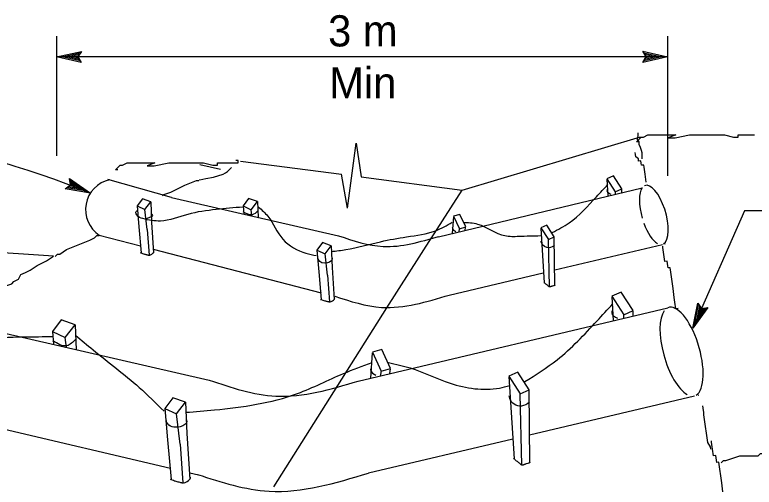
# Model space of a CAD drawing. Extents: x 6707406 to 6714471, y 1868570 to 1872341.
# Drawn here: x 6707735.3 to 6707906.2, y 1870270 to 1870379.1 of the extents above; entities that cross this region are included whole.
import ezdxf

# ---------------------------------------------------------------- set-up
doc = ezdxf.new("R2010")
doc.units = 0
for name, color, linetype in [('56 Stg 3 Anno', 7, 'Continuous'), ('57 Undefined', 7, 'Continuous'), ('60 Nongeo Data', 7, 'Continuous')]:
    doc.layers.add(name, color=color, linetype=linetype)

msp = doc.modelspace()

# ---------------------------------------------------------------- linework, layer by layer
at = {"layer": '56 Stg 3 Anno'}
for p, q in [((6707744.92, 1870374.22), (6707744.92, 1870346.59)), ((6707886.21, 1870374.22), (6707886.21, 1870341.97)), ((6707744.93, 1870369.42), (6707750.7, 1870370.68)), ((6707750.7, 1870370.68), (6707749.92, 1870369.4)), ((6707750.7, 1870370.68), (6707750.7, 1870370.68)), ((6707881.22, 1870369.42), (6707880.45, 1870370.7)), ((6707880.45, 1870370.7), (6707880.45, 1870370.7)), ((6707880.45, 1870370.7), (6707886.21, 1870369.41)), ((6707886.21, 1870369.41), (6707744.92, 1870369.42)), ((6707750.69, 1870368.11), (6707744.93, 1870369.42)), ((6707744.93, 1870369.42), (6707744.93, 1870369.42)), ((6707750.48, 1870368.46), (6707746.26, 1870369.42)), ((6707746.27, 1870369.42), (6707750.47, 1870370.33)), ((6707747.58, 1870369.41), (6707750.3, 1870370)), ((6707750.26, 1870368.8), (6707747.58, 1870369.41)), ((6707748.91, 1870369.4), (6707750.07, 1870369.66)), ((6707750.09, 1870369.14), (6707748.91, 1870369.4)), ((6707749.92, 1870369.4), (6707750.69, 1870368.11)), ((6707880.45, 1870368.14), (6707881.22, 1870369.42)), ((6707886.21, 1870369.41), (6707880.45, 1870368.14)), ((6707880.66, 1870370.36), (6707884.88, 1870369.42)), ((6707884.87, 1870369.41), (6707880.67, 1870368.48)), ((6707883.56, 1870369.42), (6707880.84, 1870368.82)), ((6707880.88, 1870370.02), (6707883.56, 1870369.42)), ((6707881.05, 1870369.68), (6707882.23, 1870369.42)), ((6707882.23, 1870369.42), (6707881.07, 1870369.16)), ((6707886.21, 1870369.41), (6707886.21, 1870369.41)), ((6707750.69, 1870368.11), (6707750.69, 1870368.11)), ((6707880.45, 1870368.14), (6707880.45, 1870368.14)), ((6707748.17, 1870339.83), (6707747.94, 1870341.31)), ((6707747.94, 1870341.31), (6707747.94, 1870341.31)), ((6707747.94, 1870341.31), (6707752.8, 1870337.97)), ((6707748.01, 1870340.92), (6707751.57, 1870338.47)), ((6707748.08, 1870340.52), (6707750.34, 1870338.96)), ((6707748.12, 1870340.14), (6707749.11, 1870339.46)), ((6707746.98, 1870338.94), (6707748.17, 1870339.83)), ((6707752.8, 1870337.97), (6707746.98, 1870338.94)), ((6707746.98, 1870338.94), (6707746.98, 1870338.94)), ((6707751.56, 1870338.47), (6707747.32, 1870339.17)), ((6707750.34, 1870338.96), (6707747.6, 1870339.42)), ((6707749.11, 1870339.46), (6707747.94, 1870339.65)), ((6707752.8, 1870337.97), (6707752.8, 1870337.97)), ((6707903.94, 1870333.87), (6707892, 1870306.77)), ((6707954.76, 1870333.87), (6707903.94, 1870333.87)), ((6707892, 1870306.77), (6707893.15, 1870312.55)), ((6707893.15, 1870312.55), (6707893.15, 1870312.55)), ((6707893.15, 1870312.55), (6707894.01, 1870311.34)), ((6707895.5, 1870311.52), (6707892, 1870306.77)), ((6707892.53, 1870307.99), (6707893.37, 1870312.21)), ((6707895.1, 1870311.47), (6707892.53, 1870307.98)), ((6707893.07, 1870309.19), (6707893.61, 1870311.92)), ((6707894.69, 1870311.4), (6707893.07, 1870309.19)), ((6707893.6, 1870310.41), (6707893.84, 1870311.57)), ((6707894.32, 1870311.38), (6707893.6, 1870310.41)), ((6707894.01, 1870311.34), (6707895.5, 1870311.52)), ((6707895.5, 1870311.52), (6707895.5, 1870311.52)), ((6707892, 1870306.77), (6707892, 1870306.77))]:
    msp.add_line(p, q, dxfattribs=at)
msp.add_ellipse((6707692.49, 1870326.8), major_axis=(94.95, -17.15), ratio=0.279834, start_param=0.934096, end_param=2.086505, dxfattribs=at)
at = {"layer": '60 Nongeo Data'}
for p, q in [((6707812.25, 1870334.5), (6707814.21, 1870349.45)), ((6707814.21, 1870349.45), (6707815.39, 1870341.71)), ((6707812.25, 1870334.5), (6707810.8, 1870342.3)), ((6707771.53, 1870336.96), (6707756.84, 1870341.13)), ((6707831.54, 1870327.45), (6707838.68, 1870338.66)), ((6707833.26, 1870327.86), (6707880.33, 1870339.18)), ((6707771.53, 1870336.96), (6707810.12, 1870328.11)), ((6707766.73, 1870335.95), (6707766.94, 1870331.19)), ((6707791.39, 1870335.99), (6707791.55, 1870332.34)), ((6707754.85, 1870328.22), (6707764.35, 1870325.76)), ((6707765.91, 1870329.52), (6707766.35, 1870323.63)), ((6707821.34, 1870311.42), (6707831.63, 1870327.59)), ((6707885.56, 1870326.22), (6707885.65, 1870326.24)), ((6707767.26, 1870325), (6707806.09, 1870314.93)), ((6707808.47, 1870325.81), (6707808.69, 1870320.79)), ((6707860.11, 1870320.2), (6707885, 1870326.11)), ((6707764.54, 1870324.13), (6707764.39, 1870324.32)), ((6707835.73, 1870314.42), (6707857.43, 1870319.57)), ((6707807.61, 1870319.03), (6707808.08, 1870312.84)), ((6707809.96, 1870293.53), (6707821.34, 1870311.42)), ((6707814.7, 1870294.54), (6707886.25, 1870311.46)), ((6707718.18, 1870308.99), (6707780.25, 1870294.75)), ((6707749.27, 1870307.56), (6707749.52, 1870301.77)), ((6707795.21, 1870270.09), (6707809.96, 1870293.53)), ((6707854.3, 1870282.12), (6707892.42, 1870291.13)), ((6707893.26, 1870291.31), (6707893.39, 1870291.33)), ((6707709.15, 1870289.03), (6707771.34, 1870274.43)), ((6707774.76, 1870289.64), (6707775.07, 1870282.46)), ((6707817.03, 1870273.32), (6707850.44, 1870281.21)), ((6707773.52, 1870279.94), (6707774.19, 1870271.07)), ((6707775.77, 1870273.38), (6707777.75, 1870272.92))]:
    msp.add_line(p, q, dxfattribs=at)
for points in [[(6707880.34, 1870345.86), (6707880.34, 1870347.23), (6707880.2, 1870347.78), (6707879.92, 1870348.46), (6707879.65, 1870349.15), (6707879.65, 1870349.42), (6707879.65, 1870349.7), (6707879.51, 1870350.11), (6707879.24, 1870350.25), (6707879.24, 1870350.38), (6707879.24, 1870350.52), (6707879.24, 1870350.66), (6707879.24, 1870350.79), (6707879.38, 1870351.07), (6707879.38, 1870351.2), (6707879.38, 1870351.34), (6707879.38, 1870351.48), (6707879.38, 1870351.62), (6707879.38, 1870351.75), (6707879.38, 1870351.85)], [(6707815.39, 1870341.71), (6707838.68, 1870338.66), (6707879.9, 1870350.92)], [(6707879.52, 1870349.8), (6707878.98, 1870349.8), (6707879.52, 1870350.33), (6707880.05, 1870350.86), (6707880.59, 1870350.86), (6707881.66, 1870351.4), (6707882.73, 1870351.4), (6707883.26, 1870351.4), (6707884.33, 1870351.4), (6707885.41, 1870351.4), (6707885.94, 1870351.4), (6707886.48, 1870351.4), (6707887.55, 1870351.4), (6707888.08, 1870351.4), (6707886.34, 1870350.73), (6707887.95, 1870350.73), (6707891.29, 1870351.4), (6707891.83, 1870351.4), (6707892.36, 1870351.4), (6707892.9, 1870351.4), (6707893.43, 1870351.4), (6707893.97, 1870351.4), (6707894.5, 1870351.4), (6707895.04, 1870351.4), (6707895.57, 1870351.4), (6707896.65, 1870351.4), (6707897.72, 1870351.4), (6707898.79, 1870351.4), (6707899.32, 1870351.4), (6707901.46, 1870350.86), (6707902.53, 1870350.86), (6707902.53, 1870351.4), (6707903.6, 1870351.4), (6707904.14, 1870351.4), (6707904.67, 1870351.4), (6707905.21, 1870351.4), (6707905.74, 1870351.4), (6707906.28, 1870351.4)], [(6707881.24, 1870340.45), (6707880.99, 1870342.32), (6707880.92, 1870342.85), (6707880.85, 1870343.38), (6707880.78, 1870343.91), (6707880.71, 1870344.44), (6707880.18, 1870344.37), (6707880.11, 1870344.9), (6707880.04, 1870345.43), (6707879.51, 1870345.35), (6707879.44, 1870345.88), (6707878.83, 1870346.34), (6707878.76, 1870346.87), (6707878.71, 1870347.31)], [(6707759.13, 1870343.33), (6707758.6, 1870343.33), (6707759.13, 1870343.86), (6707759.67, 1870344.4), (6707760.2, 1870344.4), (6707761.27, 1870344.93), (6707762.34, 1870344.93), (6707762.88, 1870344.93), (6707763.95, 1870344.93), (6707765.02, 1870344.93), (6707765.55, 1870344.93), (6707766.09, 1870344.93), (6707767.16, 1870344.93), (6707767.69, 1870344.93), (6707765.95, 1870344.26), (6707767.56, 1870344.26), (6707770.91, 1870344.93), (6707771.44, 1870344.93), (6707771.98, 1870344.93), (6707772.51, 1870344.93), (6707773.05, 1870344.93), (6707773.58, 1870344.93), (6707774.12, 1870344.93), (6707774.65, 1870344.93), (6707775.19, 1870344.93), (6707776.26, 1870344.93), (6707777.33, 1870344.93), (6707778.4, 1870344.93), (6707778.93, 1870344.93), (6707781.08, 1870344.4), (6707782.15, 1870344.4), (6707782.15, 1870344.93), (6707783.22, 1870344.93), (6707783.75, 1870344.93), (6707784.29, 1870344.93), (6707784.82, 1870344.93), (6707785.36, 1870344.93), (6707785.89, 1870344.93), (6707786.43, 1870344.93), (6707786.43, 1870344.93), (6707786.96, 1870344.93), (6707786.96, 1870345.47), (6707786.43, 1870345.47)], [(6707787.52, 1870345.35), (6707810.8, 1870342.3)], [(6707778.07, 1870341.01), (6707778.01, 1870341.01), (6707778.07, 1870341.01), (6707778.79, 1870341.18), (6707779.46, 1870341.29), (6707781.25, 1870341.62), (6707783.49, 1870342.35), (6707784.05, 1870342.63), (6707784.49, 1870342.96), (6707785.11, 1870343.52), (6707785.41, 1870343.86)], [(6707778.05, 1870344.55), (6707782.83, 1870343.47)], [(6707769.45, 1870337.3), (6707769.8, 1870337.65), (6707771.41, 1870338.18), (6707772.48, 1870338.72), (6707773.55, 1870339.25), (6707774.62, 1870339.79), (6707777.29, 1870340.86), (6707777.83, 1870340.86), (6707777.84, 1870340.86)], [(6707872.16, 1870341.18), (6707872.4, 1870337.34)], [(6707874.13, 1870337.74), (6707874.12, 1870338.24)], [(6707875.62, 1870338.09), (6707875.61, 1870338.92)], [(6707763.58, 1870334.99), (6707763.99, 1870330.2)], [(6707788.07, 1870334.98), (6707788.23, 1870333.13)], [(6707765.89, 1870329.52), (6707765.91, 1870329.52), (6707765.36, 1870334.17)], [(6707790.12, 1870332.68), (6707789.95, 1870334.12)], [(6707836.72, 1870332.55), (6707836.42, 1870328.64)], [(6707763.99, 1870330.2), (6707764.54, 1870324.13)], [(6707766.94, 1870331.19), (6707767.38, 1870324.18)], [(6707838.02, 1870329.02), (6707838.1, 1870329.68)], [(6707839.42, 1870329.35), (6707839.52, 1870330.1)], [(6707856.89, 1870329.85), (6707857.7, 1870317.24)], [(6707744.64, 1870323.34), (6707745.15, 1870323.85), (6707745.69, 1870323.85), (6707747.29, 1870324.92), (6707749.97, 1870325.99), (6707752.65, 1870327.06), (6707753.72, 1870327.59), (6707754.25, 1870328.13), (6707754.81, 1870328.13)], [(6707858.89, 1870316.27), (6707858.66, 1870327.2)], [(6707860.12, 1870316.66), (6707860.01, 1870327.82)], [(6707718.5, 1870308.92), (6707720.15, 1870310.57), (6707721.75, 1870311.1), (6707722.82, 1870311.63), (6707723.89, 1870312.17), (6707724.96, 1870312.7), (6707727.64, 1870313.77), (6707728.18, 1870313.77), (6707729.25, 1870314.31), (6707729.25, 1870314.84), (6707729.78, 1870314.84), (6707731.39, 1870315.38), (6707732.99, 1870316.45), (6707734.6, 1870316.98), (6707735.13, 1870317.51), (6707736.2, 1870318.05), (6707736.74, 1870319.12), (6707737.81, 1870319.65), (6707738.88, 1870320.19), (6707740.49, 1870321.26), (6707742.63, 1870322.32), (6707744.23, 1870323.39), (6707726.78, 1870324.51)], [(6707805.15, 1870324.8), (6707805.59, 1870319.75)], [(6707888.62, 1870311.27), (6707888.09, 1870311.2), (6707888.02, 1870311.73), (6707887.95, 1870312.26), (6707887.88, 1870312.79), (6707887.81, 1870313.32), (6707887.74, 1870313.84), (6707887.46, 1870315.96), (6707887.31, 1870317.02), (6707887.24, 1870317.55), (6707887.17, 1870318.08), (6707887.1, 1870318.61), (6707887.03, 1870319.14), (6707886.96, 1870319.67), (6707886.89, 1870320.2), (6707886.82, 1870320.73), (6707886.29, 1870320.66), (6707886.22, 1870321.19), (6707886.15, 1870321.72), (6707886.07, 1870322.25), (6707885.54, 1870322.18), (6707885.47, 1870322.71), (6707885.4, 1870323.24), (6707885.33, 1870323.77), (6707885.26, 1870324.3), (6707885.19, 1870324.83), (6707885.12, 1870325.36), (6707885.08, 1870325.68)], [(6707764.37, 1870324.18), (6707764.52, 1870324.13), (6707764.87, 1870324.03), (6707765.07, 1870323.93), (6707765.12, 1870323.93), (6707765.27, 1870323.88), (6707765.42, 1870323.83), (6707765.57, 1870323.78), (6707765.72, 1870323.78), (6707765.87, 1870323.73), (6707765.98, 1870323.68), (6707766.13, 1870323.68), (6707766.18, 1870323.63), (6707766.23, 1870323.63), (6707766.43, 1870323.63), (6707766.48, 1870323.58), (6707766.53, 1870323.63), (6707766.68, 1870323.68), (6707766.99, 1870323.83)], [(6707766.98, 1870323.83), (6707767.18, 1870323.98), (6707767.33, 1870324.13), (6707767.38, 1870324.18), (6707767.44, 1870324.23), (6707767.49, 1870324.38), (6707767.54, 1870324.38), (6707767.54, 1870324.38), (6707767.49, 1870324.38)], [(6707807.58, 1870319.04), (6707807.61, 1870319.03), (6707807.03, 1870323.93)], [(6707805.59, 1870319.75), (6707806.16, 1870313.36)], [(6707808.69, 1870320.79), (6707809.16, 1870313.42)], [(6707860.15, 1870316.68), (6707860.14, 1870316.67), (6707860.11, 1870316.65), (6707860.03, 1870316.63), (6707859.98, 1870316.61), (6707859.88, 1870316.57), (6707859.81, 1870316.54), (6707859.62, 1870316.5), (6707859.53, 1870316.48), (6707859.44, 1870316.44), (6707859.41, 1870316.43), (6707859.35, 1870316.4), (6707859.32, 1870316.4), (6707859.28, 1870316.38), (6707859.25, 1870316.38), (6707859.22, 1870316.36), (6707859.19, 1870316.35), (6707859.15, 1870316.33), (6707859.12, 1870316.31), (6707859.09, 1870316.3), (6707859.08, 1870316.29), (6707859.03, 1870316.28), (6707859.01, 1870316.27), (6707858.98, 1870316.27), (6707858.96, 1870316.27), (6707858.94, 1870316.27), (6707858.93, 1870316.27), (6707858.91, 1870316.27), (6707858.9, 1870316.26), (6707858.89, 1870316.26), (6707858.87, 1870316.26), (6707858.87, 1870316.27), (6707858.86, 1870316.28), (6707858.85, 1870316.3), (6707858.82, 1870316.34), (6707858.74, 1870316.4), (6707858.65, 1870316.49), (6707858.55, 1870316.57), (6707858.43, 1870316.65), (6707858.34, 1870316.74), (6707858.24, 1870316.82), (6707858.09, 1870316.91), (6707857.98, 1870316.99), (6707857.9, 1870317.06), (6707857.83, 1870317.13), (6707857.77, 1870317.17), (6707857.72, 1870317.23), (6707857.67, 1870317.27), (6707857.65, 1870317.28), (6707857.64, 1870317.28), (6707857.64, 1870317.29), (6707857.64, 1870317.29)], [(6707805.98, 1870313.42), (6707806.14, 1870313.37), (6707806.51, 1870313.26), (6707806.72, 1870313.15), (6707806.78, 1870313.15), (6707806.94, 1870313.1), (6707807.1, 1870313.05), (6707807.25, 1870313), (6707807.41, 1870313), (6707807.57, 1870312.94), (6707807.68, 1870312.89), (6707807.84, 1870312.89), (6707807.89, 1870312.84), (6707807.94, 1870312.84), (6707808.16, 1870312.84), (6707808.21, 1870312.78), (6707808.26, 1870312.84), (6707808.42, 1870312.89), (6707808.75, 1870313.05)], [(6707808.74, 1870313.05), (6707808.95, 1870313.21), (6707809.11, 1870313.37), (6707809.16, 1870313.42), (6707809.21, 1870313.47), (6707809.27, 1870313.63), (6707809.32, 1870313.63), (6707809.32, 1870313.63), (6707809.27, 1870313.63)], [(6707873.27, 1870314.02), (6707873.62, 1870308.53)], [(6707876.09, 1870309.1), (6707876.08, 1870309.81)], [(6707878.22, 1870309.6), (6707878.21, 1870310.79)], [(6707744.01, 1870305.96), (6707744.26, 1870303.03)], [(6707747.25, 1870302.31), (6707746.98, 1870304.59)], [(6707817.95, 1870301.1), (6707817.5, 1870295.21)], [(6707822.02, 1870296.27), (6707822.17, 1870297.41)], [(6707819.91, 1870295.78), (6707820.03, 1870296.77)], [(6707849.5, 1870295.58), (6707850.72, 1870276.58)], [(6707854.37, 1870275.69), (6707854.19, 1870292.51)], [(6707852.51, 1870275.11), (6707852.16, 1870291.58)], [(6707896.2, 1870278.85), (6707896.13, 1870279.38), (6707895.46, 1870280.37), (6707895.32, 1870281.42), (6707895.17, 1870282.48), (6707894.96, 1870284.07), (6707894.82, 1870285.13), (6707894.68, 1870286.19), (6707894.61, 1870286.72), (6707894.54, 1870287.25), (6707894.39, 1870288.31), (6707894.32, 1870288.84)], [(6707770.01, 1870288.19), (6707770.63, 1870280.97)], [(6707773.49, 1870279.95), (6707773.52, 1870279.94), (6707772.7, 1870286.96)], [(6707775.07, 1870282.46), (6707775.74, 1870271.89)], [(6707770.63, 1870280.97), (6707771.46, 1870271.81)], [(6707898.99, 1870268.93), (6707898.71, 1870271.05), (6707898.57, 1870272.11), (6707898.5, 1870272.64), (6707898.42, 1870273.17), (6707898.35, 1870273.69), (6707898.28, 1870274.22), (6707898.21, 1870274.75), (6707898.14, 1870275.28), (6707898.07, 1870275.81), (6707897.54, 1870275.74), (6707897.47, 1870276.27), (6707897.4, 1870276.8), (6707897.33, 1870277.33), (6707896.8, 1870277.26), (6707896.73, 1870277.79), (6707896.66, 1870278.32), (6707896.58, 1870278.85), (6707896.51, 1870279.38), (6707896.44, 1870279.91), (6707896.37, 1870280.44), (6707896.33, 1870280.76)], [(6707898.59, 1870275.66), (6707899.12, 1870276.19), (6707899.66, 1870276.19), (6707901.26, 1870276.73), (6707902.87, 1870277.26), (6707903.41, 1870277.26), (6707903.94, 1870277.26), (6707904.48, 1870277.26), (6707905.55, 1870277.26), (6707906.08, 1870277.26), (6707907.15, 1870277.26), (6707907.69, 1870277.8), (6707908.76, 1870277.8), (6707909.29, 1870277.8), (6707910.36, 1870277.8), (6707911.43, 1870278.33), (6707913.04, 1870278.33), (6707913.58, 1870278.87), (6707914.11, 1870278.87), (6707914.65, 1870278.87), (6707915.18, 1870278.87), (6707915.18, 1870278.87), (6707915.72, 1870279.4)], [(6707854.42, 1870275.73), (6707854.39, 1870275.72), (6707854.35, 1870275.69), (6707854.23, 1870275.65), (6707854.15, 1870275.62), (6707854.01, 1870275.56), (6707853.9, 1870275.52), (6707853.62, 1870275.45), (6707853.48, 1870275.42), (6707853.34, 1870275.37), (6707853.29, 1870275.35), (6707853.21, 1870275.31), (6707853.15, 1870275.3), (6707853.1, 1870275.27), (6707853.06, 1870275.27), (6707853, 1870275.24), (6707852.96, 1870275.23), (6707852.9, 1870275.2), (6707852.86, 1870275.17), (6707852.8, 1870275.16), (6707852.79, 1870275.14), (6707852.72, 1870275.13), (6707852.69, 1870275.11), (6707852.65, 1870275.11), (6707852.62, 1870275.1), (6707852.58, 1870275.1), (6707852.57, 1870275.1), (6707852.54, 1870275.1), (6707852.52, 1870275.09), (6707852.51, 1870275.09), (6707852.48, 1870275.09), (6707852.48, 1870275.1), (6707852.47, 1870275.13), (6707852.45, 1870275.16), (6707852.4, 1870275.21), (6707852.29, 1870275.31), (6707852.15, 1870275.44), (6707851.99, 1870275.56), (6707851.82, 1870275.69), (6707851.68, 1870275.81), (6707851.53, 1870275.94), (6707851.31, 1870276.08), (6707851.14, 1870276.19), (6707851.01, 1870276.3), (6707850.91, 1870276.4), (6707850.82, 1870276.47), (6707850.75, 1870276.56), (6707850.68, 1870276.61), (6707850.65, 1870276.62), (6707850.63, 1870276.62), (6707850.63, 1870276.64), (6707850.62, 1870276.64)], [(6707771.2, 1870271.9), (6707771.42, 1870271.82), (6707771.96, 1870271.67), (6707772.26, 1870271.52), (6707772.33, 1870271.52), (6707772.56, 1870271.45), (6707772.79, 1870271.37), (6707773.02, 1870271.29), (6707773.25, 1870271.29), (6707773.47, 1870271.22), (6707773.62, 1870271.14), (6707773.85, 1870271.14), (6707773.93, 1870271.07), (6707774, 1870271.07), (6707774.31, 1870271.07), (6707774.38, 1870270.99), (6707774.46, 1870271.07), (6707774.69, 1870271.14), (6707775.16, 1870271.37)], [(6707775.14, 1870271.37), (6707775.44, 1870271.6), (6707775.67, 1870271.82), (6707775.75, 1870271.9), (6707775.82, 1870271.98), (6707775.9, 1870272.2), (6707775.98, 1870272.2), (6707775.98, 1870272.2), (6707775.9, 1870272.2)]]:
    msp.add_lwpolyline(points, dxfattribs=at)
for points in [[(6707872.16, 1870341.28), (6707874.1, 1870338.28), (6707875.61, 1870338.95), (6707873.7, 1870341.93)], [(6707763.58, 1870334.99), (6707765.36, 1870334.17), (6707766.73, 1870335.95), (6707764.81, 1870336.64)], [(6707788.07, 1870334.98), (6707789.95, 1870334.12), (6707791.39, 1870335.99), (6707789.37, 1870336.71)], [(6707836.74, 1870332.64), (6707838.09, 1870329.72), (6707839.53, 1870330.13), (6707838.19, 1870333.03)], [(6707856.9, 1870329.94), (6707858.65, 1870327.23), (6707860.01, 1870327.84), (6707858.29, 1870330.53)], [(6707805.15, 1870324.8), (6707807.03, 1870323.93), (6707808.47, 1870325.81), (6707806.45, 1870326.53)], [(6707873.28, 1870314.16), (6707876.05, 1870309.87), (6707878.22, 1870310.83), (6707875.48, 1870315.09)], [(6707744.01, 1870305.96), (6707746.98, 1870304.59), (6707749.27, 1870307.56), (6707746.07, 1870308.71)], [(6707817.98, 1870301.23), (6707820.02, 1870296.83), (6707822.19, 1870297.45), (6707820.17, 1870301.82)], [(6707849.51, 1870295.71), (6707852.14, 1870291.63), (6707854.2, 1870292.55), (6707851.6, 1870296.6)], [(6707770.01, 1870288.19), (6707772.7, 1870286.96), (6707774.76, 1870289.64), (6707771.87, 1870290.67)]]:
    msp.add_lwpolyline(points, close=True, dxfattribs=at)
msp.add_arc((6707758.76, 1870334.13), 7.09, 102.7086, 236.5226, dxfattribs=at)
for centre, major_axis, start_param, end_param in [((6707883.01, 1870332.91), (-1.99, 6.8), 3.24529, 6.331966), ((6707883.01, 1870332.91), (-1.99, 6.8), 0.295282, 1.570773), ((6707883.01, 1870332.91), (-1.99, 6.8), 1.742227, 2.754116), ((6707889.43, 1870301.33), (-2.99, 10.2), 3.24529, 6.331966), ((6707889.43, 1870301.33), (-2.99, 10.2), 0.295282, 2.754116)]:
    msp.add_ellipse(centre, major_axis=major_axis, ratio=0.392736, start_param=start_param, end_param=end_param, dxfattribs=at)
for points in [[(6707859.52, 1870328.84), (6707863.44, 1870331.08), (6707869.75, 1870337.11), (6707872.42, 1870339.91)], [(6707872.24, 1870338.89), (6707872.17, 1870338.56), (6707873.1, 1870337.7)], [(6707788.04, 1870334.72), (6707781.87, 1870334.16), (6707775.28, 1870333.04), (6707768.97, 1870331.5), (6707764.91, 1870332.06), (6707763.51, 1870332.9), (6707763.37, 1870333.74), (6707763.79, 1870333.88)], [(6707765.79, 1870332.09), (6707767.15, 1870332.96), (6707766.93, 1870333.12)], [(6707791.48, 1870333.88), (6707790.17, 1870332.92), (6707788.12, 1870333.66)], [(6707791.68, 1870334.72), (6707793.78, 1870332.62), (6707797.29, 1870327.29), (6707802.61, 1870324.07), (6707805, 1870323.51)], [(6707808.5, 1870324.49), (6707811.86, 1870324.91), (6707819.85, 1870326.73), (6707825.88, 1870327.85), (6707832.61, 1870329.26), (6707836.39, 1870331.22)], [(6707836.44, 1870330.08), (6707836.47, 1870329.83), (6707837.27, 1870329.12)], [(6707838.92, 1870331.22), (6707842.28, 1870330.8), (6707848.59, 1870328.13), (6707851.81, 1870327.99), (6707856.86, 1870328.13)], [(6707810.12, 1870328.11), (6707820.48, 1870325.63), (6707833.26, 1870327.96)], [(6707860.09, 1870325.93), (6707858.82, 1870325.33), (6707857.03, 1870326.47), (6707856.96, 1870326.89)], [(6707808.63, 1870323.01), (6707808.69, 1870322.78), (6707807.6, 1870321.87), (6707805.49, 1870322.55), (6707805.38, 1870322.95)], [(6707809.26, 1870314.14), (6707820.1, 1870311.57), (6707835.73, 1870314.42)], [(6707853.21, 1870294.41), (6707860.64, 1870299.46), (6707869.89, 1870308.43), (6707873.54, 1870312.36)], [(6707873.39, 1870310.75), (6707873.29, 1870310.28), (6707874.63, 1870309.04)], [(6707744.12, 1870304.74), (6707737.51, 1870304.68), (6707727.34, 1870304.26), (6707714.16, 1870302.03), (6707706.88, 1870300.11), (6707703.75, 1870300.71), (6707703.27, 1870301.73), (6707703.63, 1870302.45)], [(6707749.42, 1870304.22), (6707747.34, 1870302.69), (6707744.08, 1870303.86)], [(6707749.35, 1870305.14), (6707753.41, 1870301.77), (6707764.07, 1870293.08), (6707769.81, 1870287.61)], [(6707774.86, 1870287.33), (6707781.45, 1870287.89), (6707800.65, 1870291.68), (6707811.3, 1870296.3), (6707817.89, 1870298.83)], [(6707817.53, 1870297.37), (6707817.57, 1870297), (6707818.79, 1870295.92)], [(6707821.68, 1870298.83), (6707826.72, 1870297.57), (6707835.97, 1870294.06), (6707847.33, 1870292.94), (6707849.71, 1870293.5)], [(6707780.25, 1870294.75), (6707795.66, 1870291.07), (6707814.7, 1870294.54)], [(6707854.31, 1870289.67), (6707852.41, 1870288.77), (6707849.7, 1870290.49), (6707849.61, 1870291.12)], [(6707774.98, 1870285.63), (6707775.07, 1870285.31), (6707773.52, 1870284), (6707770.49, 1870284.98), (6707770.33, 1870285.55)], [(6707777.57, 1870272.96), (6707794.09, 1870269.11), (6707817.1, 1870273.3)]]:
    msp.add_spline(points, degree=3, dxfattribs=at)

# ---------------------------------------------------------------- texts
at = {"layer": '57 Undefined'}
for s, p in [('3 m', (6707807.74, 1870371.82)), ('Min', (6707808, 1870359.82))]:
    msp.add_text(s, height=7.2, dxfattribs=at).set_placement(p)

doc.saveas('drawing.dxf')
